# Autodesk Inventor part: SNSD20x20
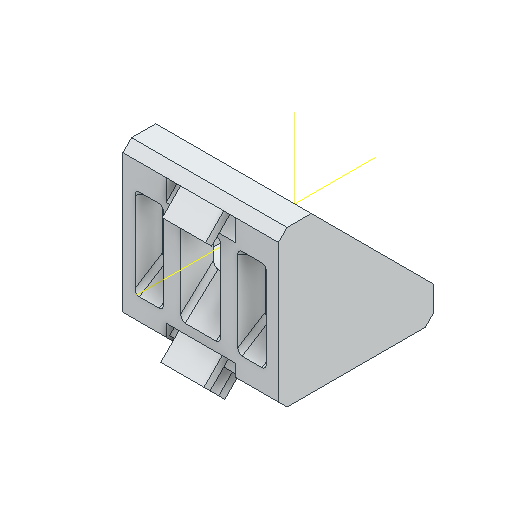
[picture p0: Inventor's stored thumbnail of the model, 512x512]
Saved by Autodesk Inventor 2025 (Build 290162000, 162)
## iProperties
Company: XTreme.ws
Created: 2015-01
Part Number: SNSD20x20
Material: Типовые
Description: STEP AP214
Document SubType Name: Modeling
Designer: skhalipa
Density: 1 g/cm^3
Appearance: Анодированный — светло-серый
Sending System: SolidWorks 2014
Preprocessor: SwSTEP 2.0
Title: SNSD.30.52.29. Óãëîâîé àëþìèíèåâûé ñîåäèíèòåëü 20õ20, ïàç 6(H23).STEP
Author: XTreme.ws
Revision Number: ANY
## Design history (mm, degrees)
feature "SNSD20x20"
node "РабОсь1"
  node "РабПлоскость1"
  node "РабПлоскость2"
node "РабОсь2"
  node "РабПлоскость3"
  node "РабПлоскость4"
node "Твердое тело1"
other parameters: "d0" = -7.1, "d1" = 7.5, "d2" = 7.5, "d3" = -7.1
